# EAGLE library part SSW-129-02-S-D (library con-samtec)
THROUGH-HOLE .025" SQ POST SOCKET Source: Samtec SSW.pdf
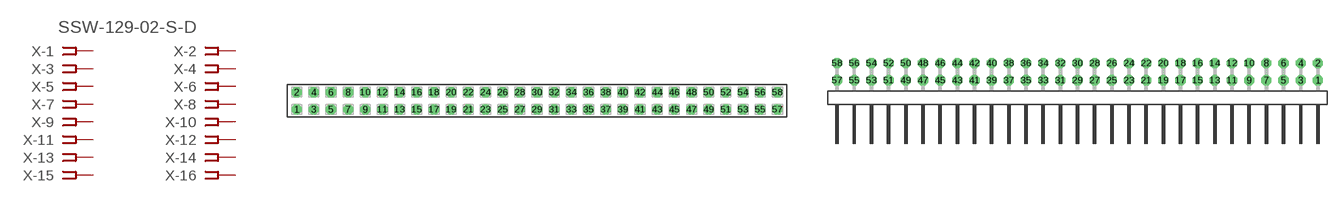
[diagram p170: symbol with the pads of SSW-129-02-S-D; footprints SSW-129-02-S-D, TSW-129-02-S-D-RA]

Designator prefix X; gates -1=FPINV -2=FPIN -3=FPIN -4=FPIN -5=FPIN -6=FPIN -7=FPIN -8=FPIN -9=FPIN -10=FPIN -11=FPIN -12=FPIN -13=FPIN -14=FPIN -15=FPIN -16=FPIN -17=FPIN -18=FPIN -19=FPIN -20=FPIN -21=FPIN -22=FPIN -23=FPIN -24=FPIN -25=FPIN -26=FPIN -27=FPIN -28=FPIN -29=FPIN -30=FPIN -31=FPIN -32=FPIN -33=FPIN -34=FPIN -35=FPIN -36=FPIN -37=FPIN -38=FPIN -39=FPIN -40=FPIN -41=FPIN -42=FPIN -43=FPIN -44=FPIN -45=FPIN -46=FPIN -47=FPIN -48=FPIN -49=FPIN -50=FPIN -51=FPIN -52=FPIN -53=FPIN -54=FPIN -55=FPIN -56=FPIN -57=FPIN -58=FPIN

## SSW-129-02-S-D (MPN: SSW-129-02-S-D; OC_FARNELL: unknown; OC_NEWARK: 11P9789)  [SSW-129-02-S-D]
1  -1:1  pas
2  -2:1  pas
3  -3:1  pas
4  -4:1  pas
5  -5:1  pas
6  -6:1  pas
7  -7:1  pas
8  -8:1  pas
9  -9:1  pas
10  -10:1  pas
11  -11:1  pas
12  -12:1  pas
13  -13:1  pas
14  -14:1  pas
15  -15:1  pas
16  -16:1  pas
17  -17:1  pas
18  -18:1  pas
19  -19:1  pas
20  -20:1  pas
21  -21:1  pas
22  -22:1  pas
23  -23:1  pas
24  -24:1  pas
25  -25:1  pas
26  -26:1  pas
27  -27:1  pas
28  -28:1  pas
29  -29:1  pas
30  -30:1  pas
31  -31:1  pas
32  -32:1  pas
33  -33:1  pas
34  -34:1  pas
35  -35:1  pas
36  -36:1  pas
37  -37:1  pas
38  -38:1  pas
39  -39:1  pas
40  -40:1  pas
41  -41:1  pas
42  -42:1  pas
43  -43:1  pas
44  -44:1  pas
45  -45:1  pas
46  -46:1  pas
47  -47:1  pas
48  -48:1  pas
49  -49:1  pas
50  -50:1  pas
51  -51:1  pas
52  -52:1  pas
53  -53:1  pas
54  -54:1  pas
55  -55:1  pas
56  -56:1  pas
57  -57:1  pas
58  -58:1  pas

## SSW-129-02-S-D-RA (MPN: SSW-129-02-S-D-RA; OC_FARNELL: unknown; OC_NEWARK: 11P9790)  [TSW-129-02-S-D-RA]
Pads as for SSW-129-02-S-D

## Footprint SSW-129-02-S-D (pad centres in mm)
THROUGH-HOLE .025" SQ POST SOCKET Source: Samtec SSW.pdf
drill 1 pad 1.5 octagon: 1 -35.56,-1.27; 2 -35.56,1.27; 3 -33.02,-1.27; 4 -33.02,1.27; 5 -30.48,-1.27; 6 -30.48,1.27; 7 -27.94,-1.27; 8 -27.94,1.27; 9 -25.4,-1.27; 10 -25.4,1.27; 11 -22.86,-1.27; 12 -22.86,1.27; 13 -20.32,-1.27; 14 -20.32,1.27; 15 -17.78,-1.27; 16 -17.78,1.27; 17 -15.24,-1.27; 18 -15.24,1.27; 19 -12.7,-1.27; 20 -12.7,1.27; 21 -10.16,-1.27; 22 -10.16,1.27; 23 -7.62,-1.27; 24 -7.62,1.27; 25 -5.08,-1.27; 26 -5.08,1.27; 27 -2.54,-1.27; 28 -2.54,1.27; 29 0,-1.27; 30 0,1.27; 31 2.54,-1.27; 32 2.54,1.27; 33 5.08,-1.27; 34 5.08,1.27; 35 7.62,-1.27; 36 7.62,1.27; 37 10.16,-1.27; 38 10.16,1.27; 39 12.7,-1.27; 40 12.7,1.27; 41 15.24,-1.27; 42 15.24,1.27; 43 17.78,-1.27; 44 17.78,1.27; 45 20.32,-1.27; 46 20.32,1.27; 47 22.86,-1.27; 48 22.86,1.27; 49 25.4,-1.27; 50 25.4,1.27; 51 27.94,-1.27; 52 27.94,1.27; 53 30.48,-1.27; 54 30.48,1.27; 55 33.02,-1.27; 56 33.02,1.27; 57 35.56,-1.27; 58 35.56,1.27

## Footprint TSW-129-02-S-D-RA (pad centres in mm)
THROUGH-HOLE .025" SQ POST HEADER Source: Samtec TSW.pdf
drill 1 pad 1.5 octagon: 1 35.56,1.524; 2 35.56,4.064; 3 33.02,1.524; 4 33.02,4.064; 5 30.48,1.524; 6 30.48,4.064; 7 27.94,1.524; 8 27.94,4.064; 9 25.4,1.524; 10 25.4,4.064; 11 22.86,1.524; 12 22.86,4.064; 13 20.32,1.524; 14 20.32,4.064; 15 17.78,1.524; 16 17.78,4.064; 17 15.24,1.524; 18 15.24,4.064; 19 12.7,1.524; 20 12.7,4.064; 21 10.16,1.524; 22 10.16,4.064; 23 7.62,1.524; 24 7.62,4.064; 25 5.08,1.524; 26 5.08,4.064; 27 2.54,1.524; 28 2.54,4.064; 29 0,1.524; 30 0,4.064; 31 -2.54,1.524; 32 -2.54,4.064; 33 -5.08,1.524; 34 -5.08,4.064; 35 -7.62,1.524; 36 -7.62,4.064; 37 -10.16,1.524; 38 -10.16,4.064; 39 -12.7,1.524; 40 -12.7,4.064; 41 -15.24,1.524; 42 -15.24,4.064; 43 -17.78,1.524; 44 -17.78,4.064; 45 -20.32,1.524; 46 -20.32,4.064; 47 -22.86,1.524; 48 -22.86,4.064; 49 -25.4,1.524; 50 -25.4,4.064; 51 -27.94,1.524; 52 -27.94,4.064; 53 -30.48,1.524; 54 -30.48,4.064; 55 -33.02,1.524; 56 -33.02,4.064; 57 -35.56,1.524; 58 -35.56,4.064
